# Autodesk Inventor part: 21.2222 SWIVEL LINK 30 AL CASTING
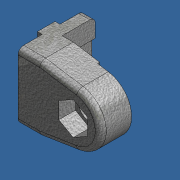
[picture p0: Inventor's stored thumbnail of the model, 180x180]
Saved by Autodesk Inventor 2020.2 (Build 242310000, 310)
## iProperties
Part Number: 21.2222 SWIVEL LINK 30 AL CASTING
Material: Aluminum 6061
Document SubType Name: Modeling
Designer: amoles
Appearance: Aluminum Cast
Mass: 29.2773 g
Surface Area: 64.819 cm^2
Volume: 10.8435 cm^3
Density: 2.7 g/cm^3
Author: amoles
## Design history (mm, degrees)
feature "Base1"
body "Solid1"
